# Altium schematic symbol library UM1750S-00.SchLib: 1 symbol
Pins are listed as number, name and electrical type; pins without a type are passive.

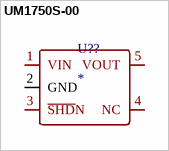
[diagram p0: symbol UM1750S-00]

## UM1750S-00
designator U??
footprint SOT-23-5
pins: 1 VIN, 2 GND, 3 ~{SHD}N, 4 NC, 5 VOUT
